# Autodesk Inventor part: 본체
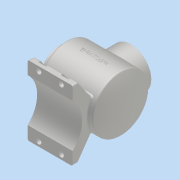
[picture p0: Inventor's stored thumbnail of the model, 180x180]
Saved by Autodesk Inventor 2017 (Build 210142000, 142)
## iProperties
Part Number: 본체
Material: 알루미늄 6061
Document SubType Name: Modeling
Designer: MRC
Density: 2.7 g/cm^3
Appearance: 알루미늄 - 평지
Mass: 1296.71 g
Surface Area: 1060.44 cm^2
Volume: 480.264 cm^3
Author: MRC
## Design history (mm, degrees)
sketch "스케치1"
  geometry: L1 (0, 36)-(12, 36); L2 (12, 36)-(12, 50); L3 (12, 50)-(108.336, 50); L4 (0, 0)-(120, 0); L5 (0, 27)-(19, 27); L6 (19, 27)-(19, 43); L7 (19, 43)-(103.887, 43); L8 (0, 36)-(0, 27); A1 r 113 centre (7, 0) between (120, 0) and (108.336, 50); A2 r 106 centre (7, 0) between (113, 0) and (103.887, 43)
  constraints: 16 end point, 4 point on circle, 3 horizontal, 3 perpendicular, 3 point on line, 2 centre point, 1 concentric, 1 parallel, 1 vertical, 1 vertical alignment
  dimensions: "d0" = 36 distance of L4.start L1.start; "d1" = 50 distance from line of L4.start L3; "d2" = 12 distance of L1.start L1.end; "d4" = 113 radius of A1; "d5" = 120 distance of L4.end L4.start; "d6" = 19 distance of L5.start L5.end; "d7" = 27 distance from line of A1.centre L5; "d8" = 86 diameter of L7 L4; "d11" = 7 distance of L4.end A2.start
revolve "회전1" sketch "스케치1" stored, may be unused: angle "d12" = 90 deg
node "작업 평면1"
sketch "스케치2"
  geometry: C1 r 36 at (-62, 0); 1 further point
  constraints: 1 centre point, 1 horizontal alignment
  dimensions: "d14" = 72 diameter of C1; "d15" = 62 distance of C1.centre point (0, 0)
extrude "돌출1" join sketch "스케치2" stored distance "d16" = 0; taper "d17" = 0 deg
sketch "스케치3"
  geometry: C1 r 27 at (0, 0); C2 r 36 at (0, 0) reference; 1 further point
  constraints: 1 centre point, 1 concentric
  dimensions: "d18" = 54 diameter of C1
extrude "돌출2" cut sketch "스케치3" distance "d19" = 45.75; taper "d20" = 0 deg
node "작업 평면3"
sketch "스케치5"
  geometry: L1 (-42.278, -26.694)-(-67, -62); L2 (-67, -62)-(-77, -62); L3 (-77, 62)-(-67, 62); L4 (-67, 62)-(-42.278, 26.694); L5 (-77, -62)-(-77, -38.5); L6 (-77, 38.5)-(-77, 62); A1 r 50 centre (0, 0) between (-42.278, -26.694) and (-42.278, 26.694) reference; A2 r 52.096 centre (-112.096, 0) between (-77, -38.5) and (-77, 38.5); 1 further point
  constraints: 12 end point, 4 perpendicular, 4 point on circle, 1 centre point, 1 horizontal, 1 horizontal alignment, 1 vertical alignment
  dimensions: "d25" = 124 distance of L2.end L3.start; "d26" = 10 distance of L1.end L2.end; "d28" = 10 distance of L3.start L3.end; "d29" = 55 deg angle of L3 L4; "d30" = 55 deg angle of L2 L1; "d35" = 77 distance from line of L6 point (0, 0); "d36" = 62 vertical distance of L3.start point (0, 0); "d37" = 17 distance edge to line of A2 L6; "d38" = 77 distance of L6.start L5.end
extrude "돌출3" join sketch "스케치5" distance "d31" = 80; taper "d32" = 0 deg
node "작업 평면4"
sketch "스케치9"
  geometry: L1 (100, 62)-(100, 38.5) reference; L2 (20, 62)-(100, 62) reference; C1 r 4.5 at (80, 54); C2 r 4.5 at (80, -54); C3 r 4.5 at (40, -54); C4 r 4.5 at (40, 54); 1 further point
  constraints: 4 centre point, 2 horizontal alignment, 2 vertical alignment
  dimensions: "d46" = 9 diameter of C1; "d47" = 20 distance from line of L1 C1.centre; "d48" = 9 diameter of C2; "d49" = 9 diameter of C3; "d50" = 9 diameter of C4; "d51" = 40 distance of C4.centre C1.centre; "d52" = 108 distance of C1.centre C2.centre; "d53" = 8 distance from line of L2 C1.centre
extrude "돌출4" cut sketch "스케치9" distance "d54" = 6; taper "d55" = 0 deg
node "작업 평면5"
sketch "스케치11"
  geometry: L1 (87, 54)-(87, 62); L2 (20, 62)-(100, 62) reference; L3 (73, 54)-(73, 62); L4 (12, 50)-(108.336, 50) reference; L5 (47, 54)-(47, 62); L6 (33, 54)-(33, 62); L7 (87, -54)-(87, -62); L8 (20, -62)-(100, -62) reference; L9 (73, -54)-(73, -62); L10 (47, -54)-(47, -62); L11 (33, -54)-(33, -62); C1 r 4.5 at (80, 54) reference; C2 r 4.5 at (40, 54) reference; C3 r 4.5 at (40, -54) reference; C4 r 4.5 at (80, -54) reference; A1 r 7 centre (80, 54) between (73, 54) and (87, 54); A2 r 7 centre (40, 54) between (33, 54) and (47, 54); A3 r 7 centre (80, -54) between (87, -54) and (73, -54); A4 r 7 centre (40, -54) between (47, -54) and (33, -54); 1 further point
  constraints: 16 end point, 12 point on line, 8 point on circle, 6 tangent, 4 centre point, 3 concentric, 3 parallel, 2 perpendicular, 1 coincident, 1 vertical
  dimensions: "d61" = 14 diameter of A3; "d62" = 14 diameter of A4; "d63" = 14 diameter of A2; "d64" = 14 diameter of A1
extrude "돌출5" cut sketch "스케치11" distance "d65" = 19.25; taper "d66" = 0 deg
sketch "스케치12"
  geometry: 2 further points
  constraints: 1 vertical alignment
  dimensions: "d67" = 32.5 distance of point (0, 32.5) point (0, 0)
hole "구멍1" sketch "스케치12" at (0, 32.5) diameter "d68" = 3.242; stored, may be unused: countersink angle "d72" = 90 deg, drill point angle "d74" = 118 deg; dims "d69" = 8, "d70" = 4, "d71" = 2, "d73" = 10
sketch "스케치13"
  geometry: C1 r 27 at (0, 0) reference; 2 further points
  constraints: 1 vertical alignment
  dimensions: "d78" = 32.5 distance of C1.centre point (0, 32.5)
hole "구멍2" sketch "스케치13" at (0, 32.5) diameter "d79" = 3.242; stored, may be unused: countersink angle "d83" = 90 deg, drill point angle "d85" = 118 deg; dims "d80" = 8, "d81" = 4, "d82" = 2, "d84" = 10
node "작업 평면6"
sketch "스케치14"
  geometry: 2 further points
  constraints: 1 horizontal alignment, 1 other
  dimensions: "d90" = 62 distance of point (0, 0) point (62, 0)
feature "엠보싱1" sketch "스케치14" dims "d91" = 0.5, "d92" = 0
chamfer "모따기1" distance "d93" = 1; stored, may be unused: second distance "d94" = 2, angle "d95" = 45 deg
fillet "모깎기1" dims "d96" = 3
fillet "모깎기2" dims "d97" = 3
fillet "모깎기3" dims "d98" = 3
fillet "모깎기4" dims "d99" = 3
fillet "모깎기5" dims "d100" = 3
node "솔리드1"
pattern_circular "원형 패턴1" dims angle "d76" = 360 deg
pattern_circular "원형 패턴2" dims angle "d87" = 360 deg
other parameters: "d13" = 65, "d27" = 77, "d45" = -77, "d60" = -71, "d89" = 51.25
